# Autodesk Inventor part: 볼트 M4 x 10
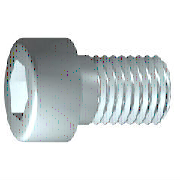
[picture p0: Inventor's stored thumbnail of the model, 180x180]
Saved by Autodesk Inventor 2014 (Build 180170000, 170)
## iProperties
IsCustomPart: 0
Created: 2012-02
Part Number: 볼트 M4 x 10
Material: 스테인리스강
Description: 6각 소켓 머리 캡 나사
Document SubType Name: Modeling
Standard: ISO 4762
Designer: mduedu
Standard Revision: Fourth edition 2004-03-01
Standards Organization: ISO
Language: ko-KR
Size Designation: M4 x 10
Categories: <MemberInstance><Categories><Category DisplayName="조임쇠" InternalName="e4da775c-781d-43d5-af7c-5136215cf5a6" Mnemonic="FSTN"><Category DisplayName="볼트" InternalN
Density: 8.08 g/cm^3
Appearance: 반광택
Author: mduedu
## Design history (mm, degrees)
sketch "스케치1"
  geometry: L1 (-1, 0)-(10, 0); L2 (10, 0)-(10, 2); L3 (10, 2)-(1.75, 2); L4 (1.75, 2)-(1.32, 2); L5 (1.32, 2)-(0, 2); L6 (0, 2)-(0, 3.5); L7 (0, 3.5)-(-4, 3.5); L8 (-4, 3.5)-(-4, 1.732); L9 (-4, 1.732)-(-2, 1.732); L10 (-2, 1.732)-(-1, 0); L11 (-6.8, 0)-(12.8, 0) reference; L12 (0, -0.7)-(0, 4.2) reference; L13 (1.75, 2)-(0, 2)
  constraints: 22 end point, 6 parallel, 2 collinear, 2 perpendicular, 1 horizontal, 1 point on line
  dimensions: "d1" = 8.25 distance from line of L3.end L2 (= GEL); "d2" = 0.42952 distance of L4.end L3.end (computed from GAL); "d3" = 4 distance between parallel lines of L8 L6 (= KOH); "d4" = 2 distance of L8.end L9.end (= INTI); "d5" = 60 deg angle of L10 L1; "d6" = 4 diameter of L3 L1 (= GD); "d7" = 4 diameter of L5 L1 (= BDM); "d8" = 3.4641 diameter of L9 L1 (= 1.1547 x SW); "d9" = 7 diameter of L7 L1 (= KOD); "d26" = 10 distance between parallel lines of L12 L2 (= NLG)
revolve "본체" sketch "스케치1" stored, may be unused: angle "d10" = 90 deg
sketch "스케치2"
  geometry: L1 (0, -4.9)-(0, 4.9) reference; L2 (-4.9, 0)-(4.9, 0) reference; L3 (1.732, 0)-(0.866, -1.5); L4 (0.866, -1.5)-(-0.866, -1.5); L5 (-0.866, -1.5)-(-1.732, 0); L6 (-1.732, 0)-(-0.866, 1.5); L7 (-0.866, 1.5)-(0.866, 1.5); L8 (0.866, 1.5)-(1.732, 0); 2 further points
  constraints: 12 end point, 1 coincident, 1 horizontal alignment, 1 point on line, 12 other
extrude "슬롯" join sketch "스케치2" stored distance "d11" = 10; taper "d12" = 0 deg
workplane "Work Plane1"
fillet "Fillet2" dims "d30" = 0.1 (= R)
body "Solid1"
fillet "모깎기1" dims "d17" = 0.4 (= RR)
feature "스레드" dims "d13" = 8.25 (= GEL), "d14" = 0
chamfer "모따기1" distance "d15" = 0.42941 (= -0.5 x SPD + 0.5 x GD); stored, may be unused: second distance "d16" = 0.42941 (= GUL), angle "d27" = 45 deg
other parameters: "GD" = 4 [user parameter; used in 2 equation terms], "NLG" = 10 [user parameter; used in 1 equation term], "GEL" = 8.25 [user parameter; used in 2 equation terms], "KOD" = 7 [user parameter; used in 1 equation term], "KOH" = 4 [user parameter; used in 1 equation term], "INTI" = 2 [user parameter; used in 1 equation term], "GAL" = 0.42941 (= 0.61345 x PTC) [user parameter; used in 1 equation term], "GUL" = 0.42941 (= 0.61345 x PTC) [user parameter; used in 1 equation term], "BDM" = 4 (= NND) [user parameter; used in 1 equation term], "SW" = 3 [user parameter; used in 2 equation terms], "RR" = 0.4 [user parameter; used in 1 equation term], "SPD" = 3.14117 (= NND - 1.2269 x PTC) [user parameter; used in 1 equation term], "d19" = 0, "d28" = 0, "d29" = 0, "R" = 0.1 [user parameter; used in 1 equation term], "TOA" = 30 deg [user parameter], "GD1" = 3.14117 (= THREADDIA - 1.2269 x PTC) [user parameter], "THREADDIA" = 4 [user parameter; used in 1 equation term], "FAWI" = 45 deg [user parameter], "TPU" = 14.28571 (computed from PTC) [user parameter], "PTC" = 0.7 [user parameter; used in 5 equation terms], "NND" = 4 [user parameter; used in 2 equation terms], "E0" = 3.465 (= 1.155 x SW) [user parameter]
